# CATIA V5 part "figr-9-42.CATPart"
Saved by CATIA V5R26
Part number: Part1
Bounding box of the stored display mesh (mm): x -60 to 60, y -70.383 to 65.913, z 0 to 125
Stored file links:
  D:\_Deepak\CATIA\CATIA V5-6R2016_Deepak\Resources\Part files\Partfiles\c09_catia_v5_6r2016_prt\figr-9-42.CATPart
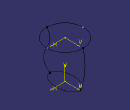
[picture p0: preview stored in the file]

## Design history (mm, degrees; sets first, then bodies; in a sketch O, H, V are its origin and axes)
Set1
  Plane1: type Offset, RefPlane xy-plane, Offset 125
Body1 (main body)
  Sketch1 on xy-plane, origin (0, 0, 0), H (1, 0, 0), V (0, 1, 0)
    ellipse A1 centre (0, 0) semi-axes 50, 30 rotation 270
    point P1 (30, 0)
    coincidence: P1 H, A1 P1
  Sketch2 on Plane1, origin (0, 0, 125), H (1, 0, 0), V (0, 1, 0)
    circle A1 centre (0, 0) radius 60
  Sketch3 on yz-plane, origin (0, 0, 0), H (0, 1, 0), V (0, 0, 1)
    arc A1 centre (-129.6632, 77.2731) radius 195.5761 from (50, 0) to (60, 125) ccw
    point P2 (50, 0)
    point P3 (60, 125)
    reference projected line E1 (-50, 0) -> (50, 0) from edge of Sketch1
    reference projected line E2 (-60, 125) -> (60, 125) from edge of Sketch2
    coincidence: P2 H, P2 E1, P3 E2
  Sketch4 on yz-plane, origin (0, 0, 0), H (0, 1, 0), V (0, 0, 1)
    spline S1 through (-50, 0) (-70, 40) (-50, 100) (-60, 125)
    reference projected line E1 (-60, 125) -> (60, 125) from edge of Sketch2
    reference projected line E2 (-50, 0) -> (50, 0) from edge of Sketch1
    point P1 (-60, 125)
    point P2 (-50, 0)
    coincidence: P1 E1, P2 E2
